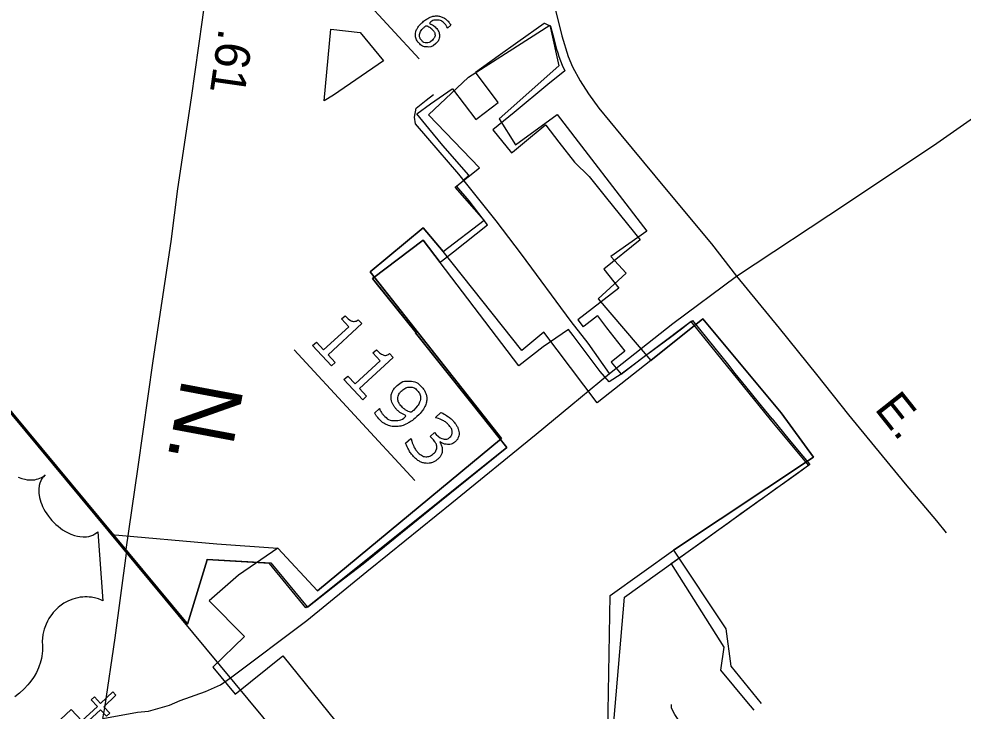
# Model space of a CAD drawing. Extents: x 1695041 to 1706254, y 786537 to 798223.
# Drawn here: x 1703274.6 to 1703431.2, y 796547.5 to 796662.3 of the extents above; entities that cross this region are included whole.
import ezdxf

# ---------------------------------------------------------------- set-up
doc = ezdxf.new("R2010")
doc.units = 0
for name, color, linetype in [('Default', 7, 'Continuous'), ('Old_Level_29', 7, 'Continuous'), ('Old_Level_32', 7, 'Continuous')]:
    doc.layers.add(name, color=color, linetype=linetype)

msp = doc.modelspace()

# ---------------------------------------------------------------- linework, layer by layer
at = {"layer": 'Default'}
for p, q in [((1703082.86, 796826.28), (1703289.9, 796576.76)), ((1703327.2, 796670.65), (1703340.99, 796655.72)), ((1703388.01, 796612.59), (1703379.38, 796605.65)), ((1703388.01, 796612.59), (1703379.38, 796605.65)), ((1703388.01, 796612.59), (1703379.38, 796605.65)), ((1703388.01, 796612.59), (1703379.38, 796605.65)), ((1703388.01, 796612.59), (1703379.38, 796605.65)), ((1703388.01, 796612.59), (1703379.38, 796605.65)), ((1703388.01, 796612.59), (1703379.38, 796605.65)), ((1703388.01, 796612.59), (1703379.38, 796605.65)), ((1703379.38, 796605.65), (1703388.01, 796612.59)), ((1703320.24, 796607.44), (1703340.26, 796585.76)), ((1703317.53, 796574.53), (1703311.01, 796570.02)), ((1703317.53, 796574.53), (1703311.01, 796570.02)), ((1703324.09, 796567.42), (1703317.53, 796574.53)), ((1703324.09, 796567.42), (1703317.53, 796574.53)), ((1703324.09, 796567.42), (1703317.53, 796574.53)), ((1703324.09, 796567.42), (1703317.53, 796574.53)), ((1703317.53, 796574.53), (1703324.09, 796567.42))]:
    msp.add_line(p, q, dxfattribs=at)
for points in [[(1702807.76, 797162.38), (1703001.1, 796924.8), (1703349.84, 796504.53)], [(1702807.76, 797162.38), (1703001.1, 796924.8), (1703349.84, 796504.53)], [(1703083.28, 796825.8), (1703083.28, 796825.8), (1703172.11, 796719.11), (1703302.41, 796562.08)], [(1703083.28, 796825.8), (1703083.28, 796825.8), (1703172.11, 796719.11), (1703302.41, 796562.08)], [(1703302.56, 796561.89), (1703172.11, 796719.11), (1703083.28, 796825.8)], [(1703302.56, 796561.89), (1703172.11, 796719.11), (1703083.28, 796825.8)], [(1703326.3, 796660.64), (1703331.19, 796660.07), (1703335.03, 796655.39), (1703326.75, 796649.68), (1703325.2, 796648.74), (1703326.3, 796660.64)], [(1703344.46, 796621.91), (1703344.69, 796622.11), (1703346.68, 796623.69), (1703352.32, 796628.18), (1703349.25, 796632.15), (1703347.21, 796634.54), (1703349.24, 796636.43), (1703344.9, 796641.35), (1703342.55, 796644.18), (1703340.57, 796646.6), (1703342.88, 796648.23), (1703346.46, 796650.76), (1703346.5, 796650.72), (1703350.39, 796645.67), (1703350.59, 796645.83), (1703354.09, 796648.48), (1703350.34, 796653.52), (1703354.07, 796656.19), (1703357.36, 796658.53), (1703361.71, 796661.63), (1703361.77, 796661.61), (1703362.78, 796661.14), (1703363.35, 796658.86), (1703363.69, 796657.46), (1703363.95, 796656.74), (1703364.16, 796656.12), (1703364.67, 796654.65), (1703365.13, 796653.74), (1703362.33, 796651.44), (1703356.71, 796646.83), (1703353.21, 796643.96), (1703356.28, 796640.09), (1703356.48, 796640.25), (1703359.77, 796642.97), (1703361.92, 796644.75), (1703361.97, 796644.69), (1703364.14, 796641.91), (1703366.73, 796638.58), (1703369.2, 796636.17), (1703372.07, 796632.6), (1703377.64, 796625.66), (1703371.6, 796620.82), (1703374.1, 796617.67), (1703367.31, 796612.42), (1703368.16, 796611.26), (1703368.36, 796611.41), (1703370.54, 796613.1), (1703370.58, 796613.05), (1703372.07, 796611.1), (1703375.08, 796607.19), (1703372.85, 796605.37), (1703374.48, 796603.36)], [(1703344.46, 796621.91), (1703344.69, 796622.11), (1703346.68, 796623.69), (1703352.32, 796628.18), (1703349.25, 796632.15), (1703347.21, 796634.54), (1703349.24, 796636.43), (1703344.9, 796641.35), (1703342.55, 796644.18), (1703340.57, 796646.6), (1703342.88, 796648.23), (1703346.46, 796650.76), (1703346.5, 796650.72), (1703350.39, 796645.67), (1703350.59, 796645.83), (1703354.09, 796648.48), (1703350.34, 796653.52), (1703354.07, 796656.19), (1703357.36, 796658.53), (1703361.71, 796661.63), (1703361.77, 796661.61), (1703362.78, 796661.14), (1703363.35, 796658.86), (1703363.69, 796657.46), (1703363.95, 796656.74), (1703364.16, 796656.12), (1703364.67, 796654.65), (1703365.13, 796653.74), (1703362.33, 796651.44), (1703356.71, 796646.83), (1703353.21, 796643.96), (1703356.28, 796640.09), (1703356.48, 796640.25), (1703359.77, 796642.97), (1703361.92, 796644.75), (1703361.97, 796644.69), (1703364.14, 796641.91), (1703366.73, 796638.58), (1703369.2, 796636.17), (1703372.07, 796632.6), (1703377.64, 796625.66), (1703371.6, 796620.82), (1703374.1, 796617.67), (1703367.31, 796612.42), (1703368.16, 796611.26), (1703368.36, 796611.41), (1703370.54, 796613.1), (1703370.58, 796613.05), (1703372.07, 796611.1), (1703375.08, 796607.19), (1703372.85, 796605.37), (1703374.48, 796603.36)], [(1703344.97, 796623.76), (1703351.73, 796628.93), (1703346.93, 796634.42), (1703350.96, 796637.61), (1703342.53, 796646.45), (1703349.14, 796652.68), (1703362.65, 796661.29), (1703364.17, 796654.53), (1703354.22, 796645.78), (1703356.95, 796641.42), (1703363.85, 796646.5), (1703378.72, 796627.14), (1703372.75, 796622.92), (1703375.31, 796620.14), (1703370.68, 796615.86), (1703379.38, 796605.65)], [(1703346.22, 796661.31), (1703345.67, 796660.81), (1703345.65, 796660.84)], [(1703372.53, 796603.5), (1703369, 796608.51), (1703366.21, 796612.1), (1703357.93, 796623.29), (1703353.77, 796628.83), (1703347.55, 796636.6), (1703342.41, 796642.56), (1703340.37, 796644.93), (1703340.18, 796646.06), (1703340.45, 796647.55), (1703342.12, 796648.88), (1703343.33, 796649.8)], [(1703344.97, 796623.76), (1703341.64, 796627.66), (1703332.85, 796620.35), (1703354.62, 796592.7), (1703324.09, 796567.42)], [(1703344.97, 796623.76), (1703341.64, 796627.66), (1703332.85, 796620.35), (1703354.62, 796592.7), (1703324.09, 796567.42)], [(1703324.09, 796567.42), (1703354.62, 796592.7), (1703332.85, 796620.35), (1703341.64, 796627.66), (1703344.97, 796623.76)], [(1703322.38, 796564.76), (1703322.43, 796564.71), (1703327.72, 796568.87), (1703331.68, 796571.93), (1703344.35, 796582.21), (1703355.52, 796591.2), (1703349.52, 796598.73), (1703340.37, 796610.23), (1703340.45, 796610.27), (1703334.06, 796618.23), (1703333.22, 796619.28), (1703341.64, 796625.62), (1703344.43, 796621.9), (1703344.46, 796621.91)], [(1703322.38, 796564.76), (1703322.43, 796564.71), (1703327.72, 796568.87), (1703331.68, 796571.93), (1703344.35, 796582.21), (1703355.52, 796591.2), (1703349.52, 796598.73), (1703340.37, 796610.23), (1703340.45, 796610.27), (1703334.06, 796618.23), (1703333.22, 796619.28), (1703341.64, 796625.62), (1703344.43, 796621.9), (1703344.46, 796621.91)], [(1703386.08, 796612.13), (1703374.48, 796603.36), (1703372.52, 796602.12), (1703371, 796603.84), (1703366.51, 796609.78), (1703365.72, 796610.82), (1703361.53, 796607.91), (1703357.53, 796604.75), (1703344.46, 796621.91), (1703341.64, 796625.62), (1703333.22, 796619.28), (1703340.45, 796610.27), (1703340.37, 796610.23), (1703355.52, 796591.2), (1703322.43, 796564.71), (1703322.38, 796564.76)], [(1703386.08, 796612.13), (1703374.48, 796603.36), (1703372.52, 796602.12), (1703371, 796603.84), (1703366.51, 796609.78), (1703365.72, 796610.82), (1703361.53, 796607.91), (1703357.53, 796604.75), (1703344.46, 796621.91), (1703341.64, 796625.62), (1703333.22, 796619.28), (1703340.45, 796610.27), (1703340.37, 796610.23), (1703355.52, 796591.2), (1703322.43, 796564.71), (1703322.38, 796564.76)], [(1703379.38, 796605.65), (1703370.49, 796598.65), (1703361.64, 796610.35), (1703358.03, 796607.3), (1703344.97, 796623.76)], [(1703379.38, 796605.65), (1703370.49, 796598.65), (1703361.64, 796610.35), (1703358.03, 796607.3), (1703344.97, 796623.76)], [(1703326.41, 796604.75), (1703323.3, 796608.12), (1703323.94, 796608.7), (1703325.13, 796607.41), (1703329.3, 796611.25), (1703328.1, 796612.55), (1703328.67, 796613.07)], [(1703330.87, 796612.42), (1703331.47, 796611.78), (1703325.87, 796606.61), (1703327.04, 796605.34), (1703326.41, 796604.75)], [(1703371.39, 796524.43), (1703371.52, 796525.89), (1703361.13, 796527.87), (1703361.9, 796530.18), (1703362.01, 796531.24), (1703362.28, 796534.24), (1703372.1, 796532.36), (1703372.88, 796541.09), (1703375.01, 796566.38), (1703386.35, 796574.51), (1703405.54, 796588.27), (1703399.28, 796595.84), (1703390.32, 796606.91), (1703386.08, 796612.13)], [(1703371.39, 796524.43), (1703371.52, 796525.89), (1703361.13, 796527.87), (1703361.9, 796530.18), (1703362.01, 796531.24), (1703362.28, 796534.24), (1703372.1, 796532.36), (1703372.88, 796541.09), (1703375.01, 796566.38), (1703386.35, 796574.51), (1703405.54, 796588.27), (1703399.28, 796595.84), (1703390.32, 796606.91), (1703386.08, 796612.13)], [(1703374.48, 796603.36), (1703378.6, 796606.51), (1703378.91, 796606.75), (1703382.64, 796609.51), (1703384.47, 796610.91), (1703385.84, 796611.94), (1703386.08, 796612.13)], [(1703374.48, 796603.36), (1703378.6, 796606.51), (1703378.91, 796606.75), (1703382.64, 796609.51), (1703384.47, 796610.91), (1703385.84, 796611.94), (1703386.08, 796612.13)], [(1703386.08, 796612.13), (1703386.32, 796612.3), (1703392.1, 796605.1), (1703393.36, 796603.52), (1703395.1, 796601.36), (1703397.2, 796598.73), (1703397.7, 796598.11), (1703399.48, 796595.99), (1703399.52, 796595.95), (1703402.37, 796592.5), (1703404.6, 796589.8), (1703405.78, 796588.38), (1703403.9, 796587.03), (1703401.57, 796585.36), (1703400.13, 796584.33), (1703398.11, 796582.87), (1703397.81, 796582.66), (1703397.45, 796582.4), (1703396.22, 796581.52), (1703394.34, 796580.18), (1703392.16, 796578.61), (1703390.29, 796577.27), (1703388.23, 796575.79), (1703383.91, 796572.69), (1703382.77, 796571.88), (1703391.54, 796558.07), (1703390.97, 796554.28), (1703395.3, 796549.06), (1703396.5, 796547.61)], [(1703386.08, 796612.13), (1703386.32, 796612.3), (1703392.1, 796605.1), (1703393.36, 796603.52), (1703395.1, 796601.36), (1703397.2, 796598.73), (1703397.7, 796598.11), (1703399.48, 796595.99), (1703399.52, 796595.95), (1703402.37, 796592.5), (1703404.6, 796589.8), (1703405.78, 796588.38), (1703403.9, 796587.03), (1703401.57, 796585.36), (1703400.13, 796584.33), (1703398.11, 796582.87), (1703397.81, 796582.66), (1703397.45, 796582.4), (1703396.22, 796581.52), (1703394.34, 796580.18), (1703392.16, 796578.61), (1703390.29, 796577.27), (1703388.23, 796575.79), (1703383.91, 796572.69), (1703382.77, 796571.88), (1703391.54, 796558.07), (1703390.97, 796554.28), (1703395.3, 796549.06), (1703396.5, 796547.61)], [(1703383.15, 796574.17), (1703406.41, 796589.59), (1703401.04, 796596.97), (1703388.01, 796612.59)], [(1703383.15, 796574.17), (1703406.41, 796589.59), (1703401.04, 796596.97), (1703388.01, 796612.59)], [(1703388.01, 796612.59), (1703401.04, 796596.97), (1703406.41, 796589.59), (1703383.15, 796574.17)], [(1703331.61, 796599.12), (1703328.5, 796602.49), (1703329.14, 796603.07), (1703330.33, 796601.78), (1703334.49, 796605.62), (1703333.3, 796606.91), (1703333.87, 796607.44)], [(1703336.07, 796606.79), (1703336.67, 796606.14), (1703331.07, 796600.98), (1703332.24, 796599.71), (1703331.61, 796599.12)], [(1703333.59, 796596.92), (1703334.4, 796597.66), (1703334.43, 796597.62)], [(1703343.75, 796596.16), (1703343.71, 796596.2), (1703344.58, 796597.01)], [(1703343.17, 796592.67), (1703342.82, 796593.05), (1703343.51, 796593.69), (1703343.78, 796593.39)], [(1703338.73, 796591.93), (1703339.6, 796592.73), (1703339.66, 796592.67)], [(1703344.45, 796592.14), (1703344.39, 796592.09)], [(1703274.47, 796586.28), (1703275.04, 796586.08), (1703275.54, 796585.96), (1703275.94, 796585.87), (1703276.6, 796585.83), (1703277.21, 796585.87), (1703277.51, 796585.94), (1703277.79, 796586.01), (1703278.32, 796586.24), (1703278.53, 796586.36), (1703278.92, 796586.67), (1703278.63, 796586.36), (1703278.47, 796586.16), (1703278.33, 796585.93), (1703278.2, 796585.67), (1703278.05, 796585.27), (1703277.96, 796584.9), (1703277.89, 796584.28), (1703277.89, 796583.94), (1703277.9, 796583.65), (1703278.01, 796582.92), (1703278.23, 796582.15), (1703278.35, 796581.78), (1703278.5, 796581.43), (1703278.71, 796581), (1703278.95, 796580.58), (1703279.21, 796580.18), (1703279.48, 796579.79), (1703279.79, 796579.4), (1703280.05, 796579.1), (1703280.38, 796578.75), (1703280.71, 796578.43), (1703281.06, 796578.13), (1703281.47, 796577.81), (1703281.81, 796577.57), (1703282.28, 796577.27), (1703282.74, 796577.03), (1703283.17, 796576.84), (1703283.77, 796576.63), (1703284.28, 796576.49), (1703284.7, 796576.43), (1703285.23, 796576.39), (1703285.8, 796576.41), (1703286.17, 796576.46), (1703286.52, 796576.56), (1703286.86, 796576.69), (1703287.19, 796576.87), (1703287.45, 796577.05), (1703287.65, 796577.23), (1703288.48, 796565.77), (1703288.28, 796565.87), (1703287.77, 796566.07), (1703287.34, 796566.2), (1703286.6, 796566.35), (1703286.25, 796566.39), (1703285.89, 796566.41), (1703285.53, 796566.41), (1703285.2, 796566.4), (1703284.75, 796566.35), (1703284.33, 796566.27), (1703283.88, 796566.17), (1703283.52, 796566.06), (1703282.8, 796565.77), (1703282.37, 796565.56), (1703282.03, 796565.36), (1703281.37, 796564.89), (1703281.07, 796564.66), (1703280.79, 796564.4), (1703280.51, 796564.11), (1703280.26, 796563.83), (1703280.01, 796563.51), (1703279.8, 796563.22), (1703279.56, 796562.85), (1703279.3, 796562.39), (1703279.08, 796561.92), (1703278.78, 796561.09), (1703278.56, 796560.16), (1703278.48, 796559.58), (1703278.46, 796559.05), (1703278.49, 796558.32), (1703278.5, 796557.92), (1703278.48, 796557.44), (1703278.38, 796556.58), (1703278.31, 796556.2), (1703278.21, 796555.8), (1703278.09, 796555.4), (1703277.96, 796554.99), (1703277.82, 796554.64), (1703277.47, 796553.88), (1703277.08, 796553.2), (1703276.86, 796552.86), (1703276.33, 796552.14), (1703276.05, 796551.8), (1703275.47, 796551.16), (1703274.7, 796550.45), (1703273.92, 796549.84)], [(1703289.9, 796576.76), (1703307.41, 796575.25), (1703317.53, 796574.53)], [(1703371.94, 796524.93), (1703372.66, 796566.64), (1703383.15, 796574.17)], [(1703371.94, 796524.93), (1703372.66, 796566.64), (1703383.15, 796574.17)], [(1703383.15, 796574.17), (1703391.82, 796561.11), (1703392.7, 796554.91), (1703397.73, 796548.74)], [(1703302.41, 796562.08), (1703302.56, 796561.89), (1703305.8, 796572.58)], [(1703302.41, 796562.08), (1703302.56, 796561.89), (1703305.8, 796572.58)], [(1703322.38, 796564.76), (1703322.19, 796564.6), (1703316.12, 796571.96), (1703305.8, 796572.58), (1703302.56, 796561.89)], [(1703322.38, 796564.76), (1703322.19, 796564.6), (1703316.12, 796571.96), (1703305.8, 796572.58), (1703302.56, 796561.89)], [(1703305.8, 796572.58), (1703305.83, 796572.69), (1703316.35, 796572.06), (1703322.38, 796564.76)], [(1703305.8, 796572.58), (1703305.83, 796572.69), (1703316.35, 796572.06), (1703322.38, 796564.76)], [(1703311.01, 796570.02), (1703306.15, 796565.77), (1703312, 796559.82), (1703306.76, 796554.78), (1703310.43, 796550.3), (1703318.36, 796556.64), (1703355.63, 796510.46), (1703360.9, 796514.74)], [(1703311.01, 796570.02), (1703306.15, 796565.77), (1703312, 796559.82), (1703306.76, 796554.78), (1703310.43, 796550.3), (1703318.36, 796556.64), (1703355.63, 796510.46), (1703360.9, 796514.74)], [(1703388.63, 796540.34), (1703387.75, 796541.43), (1703384.53, 796545.16), (1703383.38, 796546.89), (1703382.84, 796547.96), (1703382.84, 796548.56)]]:
    msp.add_lwpolyline(points, dxfattribs=at)
msp.add_lwpolyline([(1703283.23, 796547.74), (1703285.03, 796545.83), (1703287.59, 796548.23), (1703286.58, 796549.31), (1703287.12, 796549.82), (1703288.13, 796548.74), (1703290.16, 796550.64), (1703290.67, 796550.1), (1703288.64, 796548.2), (1703289.65, 796547.12), (1703289.11, 796546.61), (1703288.1, 796547.69), (1703285.53, 796545.29), (1703287.35, 796543.34), (1703283.76, 796539.98), (1703279.64, 796544.38)], close=True, dxfattribs=at)
for points in [[(1703343.72, 796658.24), (1703343.07, 796657.64), (1703342.27, 796657.69), (1703341.47, 796657.74), (1703340.9, 796658.36), (1703340.61, 796658.67), (1703340.47, 796659.02), (1703340.33, 796659.36), (1703340.34, 796659.74), (1703340.35, 796660.2), (1703340.62, 796660.69), (1703340.88, 796661.19), (1703341.43, 796661.69), (1703342, 796662.21), (1703342.55, 796662.5), (1703343.1, 796662.78), (1703343.68, 796662.83), (1703344.23, 796662.87), (1703344.78, 796662.64), (1703345.33, 796662.41), (1703345.81, 796661.89), (1703345.97, 796661.72), (1703346.06, 796661.59), (1703346.15, 796661.46), (1703346.22, 796661.31)], [(1703345.65, 796660.84), (1703345.62, 796660.96), (1703345.51, 796661.15), (1703345.4, 796661.35), (1703345.24, 796661.52), (1703344.68, 796662.13), (1703343.96, 796662.14), (1703343.24, 796662.15), (1703342.53, 796661.61), (1703342.9, 796661.5), (1703343.19, 796661.34), (1703343.48, 796661.18), (1703343.76, 796660.87), (1703344.01, 796660.6), (1703344.15, 796660.35), (1703344.29, 796660.1), (1703344.34, 796659.74), (1703344.39, 796659.33), (1703344.25, 796658.96), (1703344.1, 796658.59), (1703343.72, 796658.24)], [(1703343.16, 796658.8), (1703343.42, 796659.04), (1703343.53, 796659.28), (1703343.63, 796659.52), (1703343.59, 796659.81), (1703343.56, 796660.03), (1703343.44, 796660.21), (1703343.32, 796660.4), (1703343.16, 796660.57), (1703342.94, 796660.82), (1703342.69, 796660.97), (1703342.44, 796661.13), (1703342.12, 796661.23), (1703342.05, 796661.18), (1703341.99, 796661.13), (1703341.93, 796661.08), (1703341.84, 796661), (1703341.39, 796660.58), (1703341.22, 796660.25), (1703341.04, 796659.92), (1703341.04, 796659.62), (1703341.04, 796659.37), (1703341.12, 796659.16), (1703341.2, 796658.96), (1703341.37, 796658.78), (1703341.75, 796658.37), (1703342.22, 796658.36), (1703342.69, 796658.36), (1703343.16, 796658.8)], [(1703328.67, 796613.07), (1703328.91, 796612.81), (1703329.23, 796612.55), (1703329.56, 796612.29), (1703329.78, 796612.21), (1703330.06, 796612.11), (1703330.33, 796612.15), (1703330.59, 796612.19), (1703330.87, 796612.42)], [(1703333.87, 796607.44), (1703334.11, 796607.18), (1703334.43, 796606.92), (1703334.75, 796606.66), (1703334.98, 796606.58), (1703335.26, 796606.48), (1703335.52, 796606.52), (1703335.79, 796606.56), (1703336.07, 796606.79)], [(1703334.43, 796597.62), (1703334.48, 796597.44), (1703334.63, 796597.16), (1703334.78, 796596.89), (1703335.03, 796596.62), (1703335.88, 796595.7), (1703336.91, 796595.68), (1703337.95, 796595.67), (1703339, 796596.49), (1703338.41, 796596.66), (1703337.99, 796596.91), (1703337.57, 796597.16), (1703337.2, 796597.56), (1703336.85, 796597.94), (1703336.64, 796598.32), (1703336.42, 796598.7), (1703336.35, 796599.22), (1703336.27, 796599.82), (1703336.49, 796600.37), (1703336.71, 796600.91), (1703337.26, 796601.42), (1703338.21, 796602.3), (1703339.39, 796602.22), (1703340.56, 796602.15), (1703341.4, 796601.25), (1703341.81, 796600.8), (1703342.03, 796600.29), (1703342.24, 796599.77), (1703342.23, 796599.23), (1703342.21, 796598.55), (1703341.84, 796597.86), (1703341.47, 796597.16), (1703340.61, 796596.36)], [(1703340.01, 796597.38), (1703340.65, 796597.98), (1703340.92, 796598.47), (1703341.19, 796598.97), (1703341.19, 796599.4), (1703341.2, 796599.77), (1703341.07, 796600.07), (1703340.95, 796600.37), (1703340.71, 796600.63), (1703340.15, 796601.23), (1703339.46, 796601.23), (1703338.76, 796601.23), (1703338.08, 796600.61), (1703337.68, 796600.24), (1703337.54, 796599.9), (1703337.39, 796599.55), (1703337.45, 796599.11), (1703337.49, 796598.81), (1703337.65, 796598.54), (1703337.82, 796598.27), (1703338.07, 796598), (1703338.37, 796597.68), (1703338.77, 796597.42), (1703339.16, 796597.17), (1703339.6, 796597.03), (1703339.69, 796597.11), (1703339.78, 796597.18), (1703339.87, 796597.26), (1703340.01, 796597.38)], [(1703340.61, 796596.36), (1703339.79, 796595.61), (1703338.96, 796595.18), (1703338.12, 796594.76), (1703337.3, 796594.7), (1703336.48, 796594.64), (1703335.69, 796594.97), (1703334.9, 796595.31), (1703334.19, 796596.08), (1703333.99, 796596.29), (1703333.84, 796596.51), (1703333.68, 796596.72), (1703333.59, 796596.92)], [(1703343.78, 796593.39), (1703344.37, 796592.76), (1703344.98, 796592.63), (1703345.59, 796592.49), (1703346.1, 796592.96), (1703346.33, 796593.17), (1703346.41, 796593.43), (1703346.49, 796593.68), (1703346.44, 796593.95), (1703346.39, 796594.23), (1703346.24, 796594.47), (1703346.09, 796594.72), (1703345.85, 796594.98), (1703345.49, 796595.37), (1703344.93, 796595.69), (1703344.38, 796596), (1703343.75, 796596.16)], [(1703344.58, 796597.01), (1703345, 796596.85), (1703345.58, 796596.47), (1703346.16, 796596.08), (1703346.59, 796595.62), (1703347.01, 796595.16), (1703347.25, 796594.74), (1703347.48, 796594.32), (1703347.56, 796593.87), (1703347.64, 796593.38), (1703347.49, 796592.97), (1703347.35, 796592.55), (1703346.97, 796592.2), (1703346.46, 796591.72), (1703345.73, 796591.73), (1703345.01, 796591.74), (1703344.45, 796592.14)], [(1703344.81, 796590.82), (1703344.82, 796590.45), (1703344.67, 796590.07), (1703344.51, 796589.69), (1703344.08, 796589.3), (1703343.66, 796588.9), (1703343.16, 796588.73), (1703342.66, 796588.56), (1703342.14, 796588.59), (1703341.56, 796588.64), (1703341.03, 796588.93), (1703340.5, 796589.22), (1703340.03, 796589.73), (1703339.56, 796590.25), (1703339.22, 796590.86), (1703338.88, 796591.47), (1703338.73, 796591.93)], [(1703339.66, 796592.67), (1703339.75, 796592.1), (1703340.04, 796591.48), (1703340.33, 796590.86), (1703340.74, 796590.41), (1703340.98, 796590.15), (1703341.34, 796589.93), (1703341.71, 796589.71), (1703342.05, 796589.69), (1703342.41, 796589.67), (1703342.72, 796589.78), (1703343.03, 796589.89), (1703343.37, 796590.2), (1703343.7, 796590.51), (1703343.82, 796590.82), (1703343.94, 796591.13), (1703343.89, 796591.43), (1703343.85, 796591.74), (1703343.65, 796592.05), (1703343.45, 796592.36), (1703343.17, 796592.67)], [(1703344.39, 796592.09), (1703344.54, 796591.86), (1703344.67, 796591.5), (1703344.81, 796591.15), (1703344.81, 796590.82)]]:
    msp.add_open_spline(points, degree=3, dxfattribs=at)
at = {"layer": 'Old_Level_29'}
for points in [[(1703292.29, 796573.89), (1703294.34, 796588.01), (1703296.84, 796605.59), (1703299.81, 796625.38), (1703300.93, 796634.14), (1703303.19, 796649.26), (1703305.04, 796662.18), (1703306.98, 796676.53), (1703308.84, 796689.44), (1703308.93, 796693.01), (1703308.99, 796699.31), (1703307.85, 796716.87), (1703307.5, 796720.88)], [(1703363.53, 796663.99), (1703364.64, 796659.51), (1703365.69, 796656.13), (1703366.41, 796654.39), (1703367.68, 796652.07), (1703369.05, 796649.89), (1703370.79, 796647.52), (1703374.45, 796643.13), (1703376.33, 796640.83), (1703381.96, 796634.04), (1703389.49, 796625.02), (1703393.61, 796619.66)], [(1703393.61, 796619.66), (1703400.68, 796611.04), (1703406.88, 796603.31), (1703412.22, 796596.61), (1703421.62, 796585.21), (1703426.77, 796579.04), (1703428.4, 796577.05)], [(1703288.47, 796546.24), (1703288.81, 796548.02), (1703290.57, 796559.6), (1703292.44, 796573.7)]]:
    msp.add_lwpolyline(points, dxfattribs=at)
at = {"layer": 'Old_Level_32'}
for points in [[(1703393.61, 796619.66), (1703412.04, 796631.82), (1703426.87, 796641.71), (1703441.25, 796651.77), (1703457.65, 796662.81), (1703468.28, 796670.28), (1703472.5, 796673.05), (1703478.97, 796676.5), (1703498.59, 796685.51), (1703506.83, 796687.71), (1703510.78, 796689.24), (1703515.17, 796691.26), (1703519.2, 796693.57), (1703524.18, 796696.51), (1703532.81, 796702.93), (1703552.59, 796715.99), (1703561.22, 796720.54), (1703566.39, 796722.11), (1703571.54, 796723.26), (1703587.36, 796723.78)], [(1703372.53, 796603.5), (1703383.04, 796611.8), (1703393.61, 796619.66)], [(1703309.65, 796552.97), (1703322.36, 796562.52), (1703332.3, 796570.64), (1703335.98, 796573.6), (1703346.4, 796582.04), (1703360.36, 796593.45), (1703366.15, 796598.19), (1703372.53, 796603.5)], [(1703288.47, 796546.24), (1703294.23, 796547.27), (1703296.1, 796547.44), (1703299.56, 796548.47), (1703301.31, 796549.2), (1703305.53, 796550.72), (1703308.02, 796551.8), (1703309.65, 796552.97)]]:
    msp.add_lwpolyline(points, dxfattribs=at)

# ---------------------------------------------------------------- texts
at = {"layer": 'Default'}
for s, height, rotation, p in [('.61', 5.775, 261.8645, (1703307.78, 796660.92)), ('N.', 10.349, 259.359, (1703301.72, 796602.93)), ('E.', 5.544, 308.4689, (1703416.39, 796597.59)), ('Archdale', 6.93, 312.7091, (1703254.51, 796545.99))]:
    msp.add_text(s, height=height, rotation=rotation, dxfattribs=at).set_placement(p)

doc.saveas('drawing.dxf')
